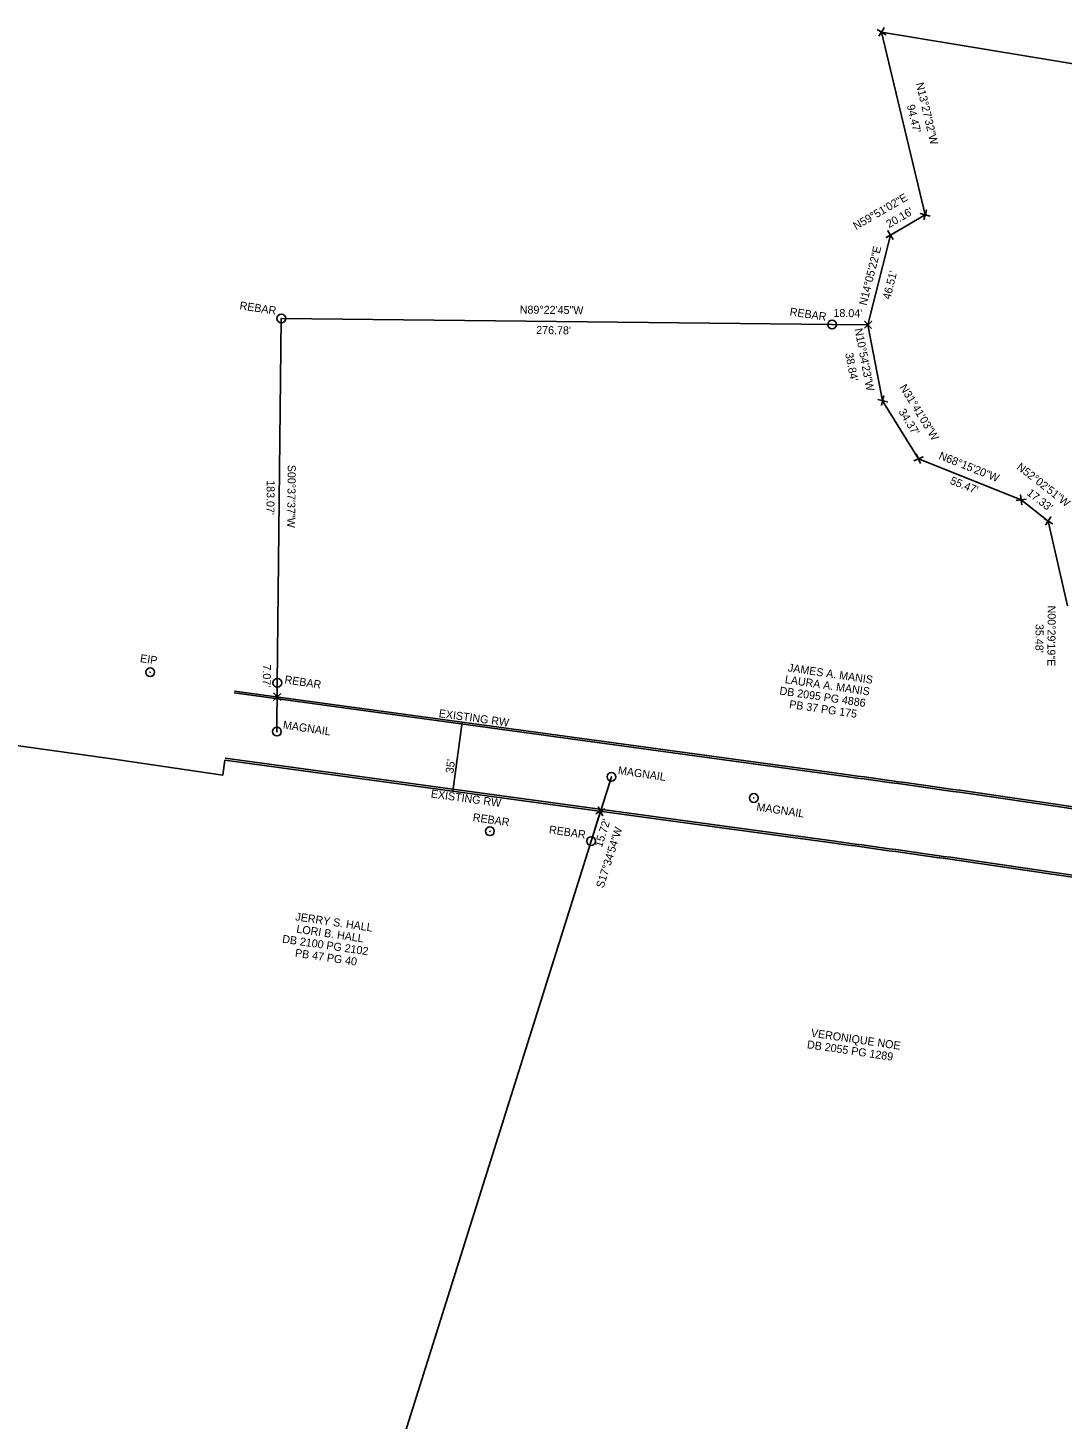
# Model space of a CAD drawing. Extents: x 1107874 to 1110849, y 645477 to 647181.
# Drawn here: x 1108530 to 1109050, y 646183 to 646882 of the extents above; entities that cross this region are included whole.
import ezdxf

# ---------------------------------------------------------------- set-up
doc = ezdxf.new("R2010")
doc.units = 0
for name, color, linetype in [('Exist Property Corner CELL', 7, 'Continuous'), ('Exist Property Iron Pin CELL', 7, 'Continuous'), ('Exist Property Line', 7, 'Continuous'), ('Exist Property Text', 7, 'Continuous'), ('Exist Right of Way Line', 7, 'Continuous'), ('Exist Right of Way Text', 7, 'Continuous')]:
    doc.layers.add(name, color=color, linetype=linetype)

msp = doc.modelspace()

# ---------------------------------------------------------------- linework, layer by layer
at = {"layer": 'Exist Property Corner CELL'}
for p, q in [((1108959.02, 646880.02), (1108959.02, 646880.02)), ((1108981, 646788.15), (1108981, 646788.15)), ((1108963.57, 646778.02), (1108963.57, 646778.02)), ((1108952.25, 646732.91), (1108952.25, 646732.91)), ((1108959.6, 646694.77), (1108959.6, 646694.77)), ((1108977.65, 646665.52), (1108977.65, 646665.52)), ((1109029.17, 646644.97), (1109029.17, 646644.97)), ((1109042.84, 646634.31), (1109042.84, 646634.31)), ((1108655.38, 646545.97), (1108655.38, 646545.97)), ((1108817.84, 646488.49), (1108817.84, 646488.49))]:
    msp.add_line(p, q, dxfattribs=at)
for points in [[(1108956.89, 646881.33), (1108961.15, 646878.71), (1108959.02, 646880.02), (1108960.33, 646882.15), (1108957.71, 646877.89)], [(1108980.36, 646785.73), (1108981.65, 646790.56), (1108981, 646788.15), (1108978.59, 646788.79), (1108983.42, 646787.5)], [(1108964.85, 646775.87), (1108962.29, 646780.17), (1108963.57, 646778.02), (1108961.43, 646776.74), (1108965.72, 646779.3)], [(1108950.46, 646731.16), (1108954.04, 646734.65), (1108952.25, 646732.91), (1108950.5, 646734.69), (1108954, 646731.12)], [(1108957.16, 646695.34), (1108962.03, 646694.19), (1108959.6, 646694.77), (1108960.17, 646697.2), (1108959.02, 646692.33)], [(1108975.35, 646664.53), (1108979.95, 646666.51), (1108977.65, 646665.52), (1108976.66, 646667.82), (1108978.64, 646663.22)], [(1109026.69, 646644.66), (1109031.65, 646645.28), (1109029.17, 646644.97), (1109028.87, 646647.45), (1109029.48, 646642.49)], [(1109040.72, 646635.64), (1109044.95, 646632.98), (1109042.84, 646634.31), (1109044.17, 646636.43), (1109041.51, 646632.2)], [(1108657.14, 646544.19), (1108653.63, 646547.76), (1108655.38, 646545.97), (1108653.6, 646544.22), (1108657.17, 646547.73)], [(1108818.99, 646486.27), (1108816.69, 646490.71), (1108817.84, 646488.49), (1108815.62, 646487.34), (1108820.06, 646489.64)]]:
    msp.add_lwpolyline(points, dxfattribs=at)
at = {"layer": 'Exist Property Iron Pin CELL'}
for centre, radius in [((1108657.45, 646736.1), 2.2), ((1108657.45, 646736.1), 0.0707), ((1108934.21, 646733.1), 2.2), ((1108934.21, 646733.1), 0.0707), ((1108591.56, 646558.34), 2.2), ((1108591.56, 646558.34), 0.0707), ((1108655.44, 646553.04), 2.2), ((1108655.44, 646553.04), 0.0707), ((1108655.24, 646528.52), 2.2), ((1108655.24, 646528.52), 0.0707), ((1108823.33, 646505.8), 2.2), ((1108823.33, 646505.8), 0.0707), ((1108894.87, 646495.17), 2.2), ((1108894.87, 646495.17), 0.0707), ((1108762.27, 646478.43), 2.2), ((1108762.27, 646478.43), 0.0707), ((1108813.09, 646473.51), 2.2), ((1108813.09, 646473.51), 0.0707)]:
    msp.add_circle(centre, radius, dxfattribs=at)
at = {"layer": 'Exist Property Line'}
for p, q in [((1108981, 646788.15), (1108959.02, 646880.02)), ((1108959.02, 646880.02), (1109713.46, 646755.51)), ((1108963.57, 646778.02), (1108981, 646788.15)), ((1108952.25, 646732.91), (1108963.57, 646778.02)), ((1108657.45, 646736.1), (1108655.44, 646553.04)), ((1108934.21, 646733.1), (1108657.45, 646736.1)), ((1108952.25, 646732.91), (1108934.21, 646733.1)), ((1108959.6, 646694.77), (1108952.25, 646732.91)), ((1108977.65, 646665.52), (1108959.6, 646694.77)), ((1109029.17, 646644.97), (1108977.65, 646665.52)), ((1109042.84, 646634.31), (1109029.17, 646644.97)), ((1109052.54, 646591.66), (1109042.84, 646634.31)), ((1108655.44, 646553.04), (1108655.24, 646528.52)), ((1108655.44, 646553.04), (1108655.38, 646545.97)), ((1108823.33, 646505.8), (1108813.09, 646473.51)), ((1108817.84, 646488.49), (1108813.09, 646473.51)), ((1108813.09, 646473.51), (1108536.6, 645593.64))]:
    msp.add_line(p, q, dxfattribs=at)
at = {"layer": 'Exist Right of Way Line'}
for p, q in [((1108633.88, 646548.91), (1108940.15, 646507.13)), ((1108633.88, 646548.91), (1108940.15, 646507.13)), ((1108633.74, 646547.92), (1108940.02, 646506.14)), ((1108629.15, 646514.23), (1108628.12, 646506.71)), ((1108629.15, 646514.23), (1108935.42, 646472.45)), ((1108629.15, 646514.23), (1108935.42, 646472.45)), ((1108629.28, 646515.22), (1108935.56, 646473.44)), ((1109049.68, 646490.57), (1109143.13, 646476.77)), ((1109049.82, 646491.56), (1109143.27, 646477.76)), ((1109044.86, 646457.92), (1109138.31, 646444.12)), ((1109044.71, 646456.93), (1109138.16, 646443.13)), ((1109044.71, 646456.93), (1109086.77, 646450.72))]:
    msp.add_line(p, q, dxfattribs=at)
msp.add_lwpolyline([(1107953.31, 646603.42), (1108019.07, 646593.53), (1108163.65, 646572.58), (1108212.99, 646565.36), (1108336.22, 646548.38), (1108440.68, 646532.91), (1108495.41, 646525.62), (1108572.22, 646514.83), (1108620.08, 646507.85), (1108628.12, 646506.71)], dxfattribs=at)
for radius in [10017.5, 10017.5, 10016.5, 9982.5, 9982.5, 9983.5]:
    msp.add_arc((1107586.36, 636581.53), radius, 81.599575, 82.233161, dxfattribs=at)
at = {"layer": 'Exist Right of Way Text'}
for p, q in [((1108743.59, 646498.62), (1108748.32, 646533.3)), ((1108748.32, 646533.3), (1108743.59, 646498.62))]:
    msp.add_line(p, q, dxfattribs=at)

# ---------------------------------------------------------------- texts
at = {"layer": 'Exist Property Text'}
for s, rotation, p in [('N13°27\'32"W', 283.45881, (1108976.27, 646854.2)), ("94.47'", 283.45881, (1108971.73, 646843.12)), ('N59°51\'02"E', 30.14936, (1108946.24, 646780.47)), ("20.16'", 30.14936, (1108962.86, 646781.43)), ('N14°05\'22"E', 75.91062, (1108951.55, 646742.39)), ("46.51'", 75.91062, (1108963.43, 646745.43)), ('REBAR', 351.59957, (1108636.29, 646740.73)), ('N89°22\'45"W', 359.37906, (1108777.24, 646738.58)), ('REBAR', 351.59957, (1108912.72, 646737.67)), ("18.04'", 359.37906, (1108934.88, 646736.87)), ("276.78'", 359.37906, (1108785.51, 646728.31)), ('N10°54\'23"W', 280.90629, (1108945.5, 646730.8)), ("38.84'", 280.90629, (1108940.75, 646718.53)), ('N31°41\'03"W', 301.68406, (1108967.97, 646701.51)), ("34.37'", 301.68406, (1108967.43, 646689.27)), ('N68°15\'20"W', 338.25545, (1108987.5, 646665.66)), ('S00°37\'37"W', 269.37303, (1108660.71, 646662.61)), ('N52°02\'51"W', 322.0474, (1109026.61, 646660.77)), ("183.07'", 269.37303, (1108650.14, 646654.87)), ("55.47'", 338.25545, (1108993.17, 646653.15)), ("17.33'", 322.0474, (1109031.72, 646647.78)), ('N00°29\'19"E', 269.51129, (1109042.6, 646591.85)), ("35.48'", 269.51129, (1109036.5, 646582.63)), ('EIP', 351.59957, (1108586.28, 646563.48)), ('JAMES A. MANIS', 351.59957, (1108911.85, 646558.78)), ("7.07'", 269.53207, (1108648.23, 646562.28)), ('REBAR', 351.59957, (1108658.88, 646552.8)), ('LAURA A. MANIS', 351.59957, (1108910.31, 646552.91)), ('DB 2095 PG 4886', 351.59957, (1108907.59, 646547.21)), ('PB 37 PG 175', 351.59957, (1108912.44, 646540.4)), ('MAGNAIL', 351.59957, (1108658.08, 646530.07)), ('MAGNAIL', 351.59957, (1108826.42, 646507.22)), ('MAGNAIL', 351.59957, (1108896.03, 646488.85)), ('REBAR', 351.59957, (1108753.47, 646483.62)), ('REBAR', 351.59957, (1108791.76, 646477.41)), ("15.72'", 72.4183, (1108818.51, 646470.03)), ('S17°34\'54"W', 72.4183, (1108819.32, 646449.59)), ('JERRY S. HALL', 351.59957, (1108664.32, 646433.7)), ('LORI B. HALL', 351.59957, (1108664.84, 646427.53)), ('DB 2100 PG 2102', 351.59957, (1108657.7, 646422.49)), ('PB 47 PG 40', 351.59957, (1108664.13, 646415.45)), ('VERONIQUE NOE', 351.59957, (1108923.37, 646375.28)), ('DB 2055 PG 1289', 351.59957, (1108921.41, 646369.47))]:
    msp.add_text(s, height=4.02, rotation=rotation, dxfattribs=at).set_placement(p)
at = {"layer": 'Exist Right of Way Text'}
for s, rotation, p in [('EXISTING RW', 352.23316, (1108736.39, 646535.83)), ("35'", 82.23316, (1108743.9, 646507.39)), ('EXISTING RW', 352.23316, (1108732.41, 646495.43))]:
    msp.add_text(s, height=4.02, rotation=rotation, dxfattribs=at).set_placement(p)

doc.saveas('drawing.dxf')
